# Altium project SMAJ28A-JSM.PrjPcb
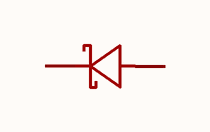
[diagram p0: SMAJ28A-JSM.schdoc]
1 sheet, 1 parts. Net scope: global (net labels, ports and power ports of the same name join across sheets).

## Sheet SMAJ28A-JSM.schdoc
size 127 x 101 mm

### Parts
D?  smaj28a-jsm  [SMA_L4.3-W2.6-LS5.1-RD]  (value not drawn)

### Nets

Not connected (* = marked no-connect by the designer): D? 1(K) 2(A)

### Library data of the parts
D? = smaj28a-jsm: 极性:单向;反向截止电压(Vrwm):28V;钳位电压:45.4V;峰值脉冲电流(Ipp):8.8A;峰值脉冲功率(Ppp):400W;击穿电压(VBR):34.4V;; Manufacturer: JSMSEMI(杰盛微); AddInBom: yes; ModelId: 1d20a911e9694ba6aaf6e9207164e4da; ModelTransform: 196.4563,102.362,0,0,0,0,0.001,-0.001,0; Polarity: 单向; Reverse Stand-Off Voltage (Vrwm): 28V; Clamping Voltage: 45.4V; Peak Pulse Current (Ipp): 8.8A; Peak Pulse Power Dissipation (Ppp): 400W; Voltage - Breakdown: 34.4V; Reverse Leakage Current (Ir): 1uA; Number of Channels: 单路; Type: TVS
